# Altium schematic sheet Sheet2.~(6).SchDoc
size A4
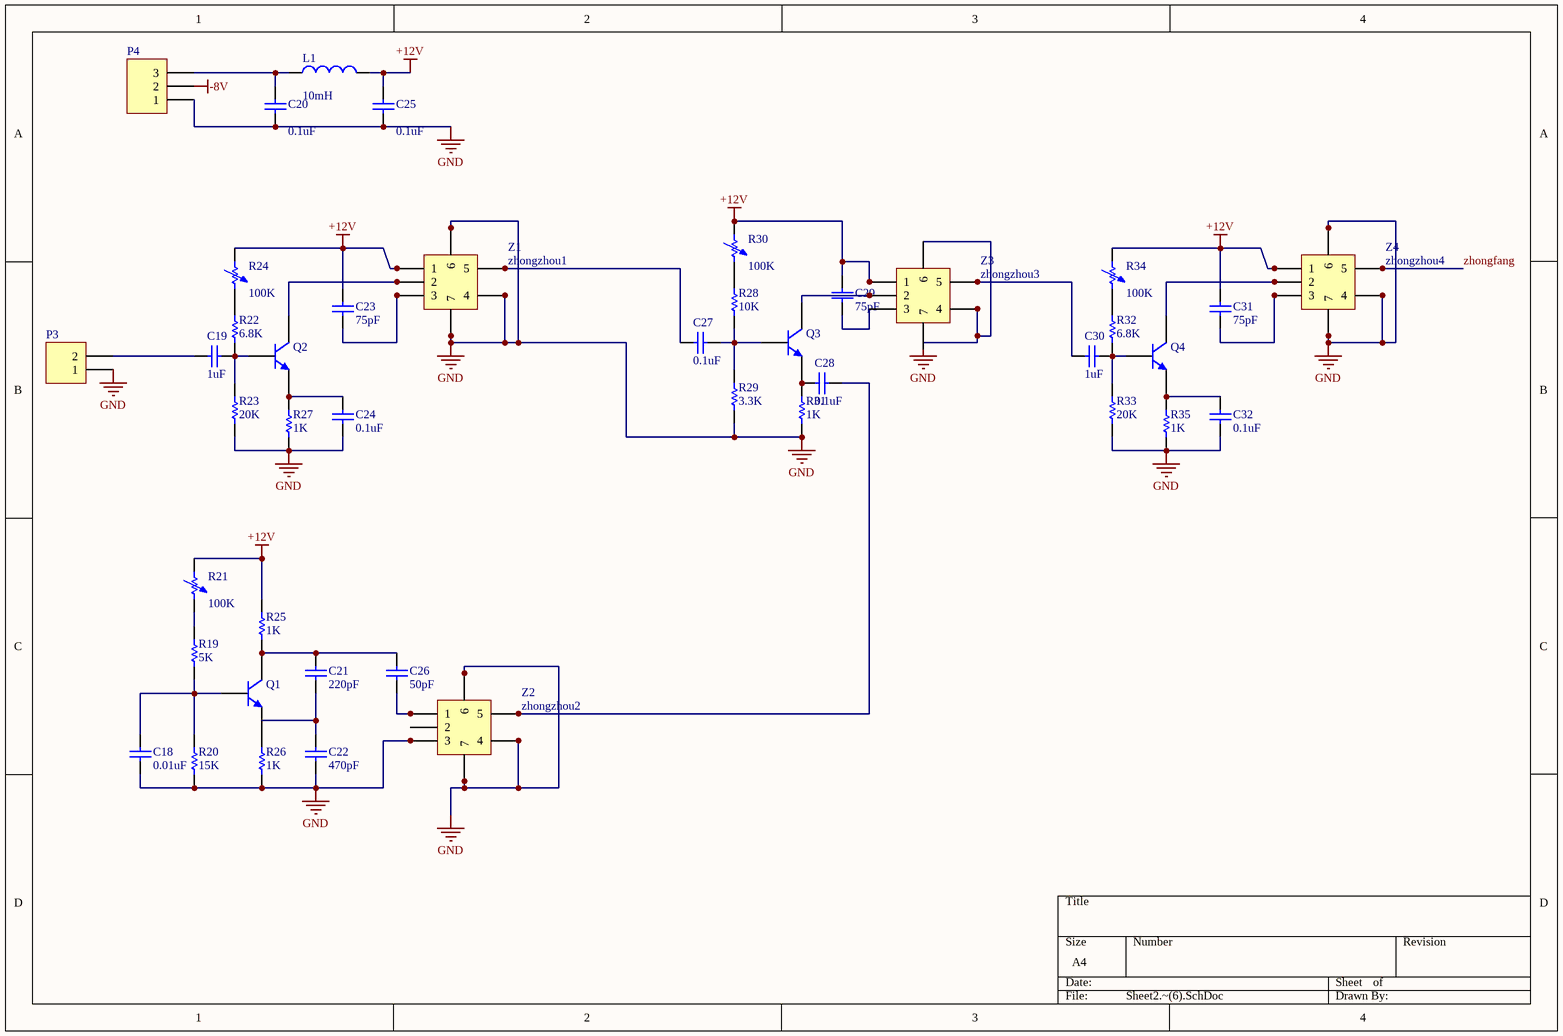
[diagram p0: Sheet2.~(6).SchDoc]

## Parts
C18  value 0.01uF  [2012[0805]]  (hidden comment: Cap)
C19  value 1uF  [2012[0805]]  (hidden comment: Cap)
C20  value 0.1uF  [2012[0805]]  (hidden comment: Cap)
C21  value 220pF  [2012[0805]]  (hidden comment: Cap)
C22  value 470pF  [2012[0805]]  (hidden comment: Cap)
C23  value 75pF  [2012[0805]]  (hidden comment: Cap)
C24  value 0.1uF  [2012[0805]]  (hidden comment: Cap)
C25  value 0.1uF  [2012[0805]]  (hidden comment: Cap)
C26  value 50pF  [2012[0805]]  (hidden comment: Cap)
C27  value 0.1uF  [2012[0805]]  (hidden comment: Cap)
C28  value 0.1uF  [2012[0805]]  (hidden comment: Cap)
C29  value 75pF  [2012[0805]]  (hidden comment: Cap)
C30  value 1uF  [2012[0805]]  (hidden comment: Cap)
C31  value 75pF  [2012[0805]]  (hidden comment: Cap)
C32  value 0.1uF  [2012[0805]]  (hidden comment: Cap)
L1  value 10mH  [0402-A]  (hidden comment: Inductor)
P3  Header 2  [HDR1X2]  (value not drawn)
P4  Header 3  [shuru]  (value not drawn)
Q1  NPN  [TO-226]  (value not drawn)
Q2  NPN  [TO-226]  (value not drawn)
Q3  NPN  [TO-226]  (value not drawn)
Q4  NPN  [TO-226]  (value not drawn)
R19  value 5K  [2012[0805]]  (hidden comment: Res1)
R20  value 15K  [2012[0805]]  (hidden comment: Res1)
R21  value 100K  [2012[0805]]  (hidden comment: Res Adj1)
R22  value 6.8K  [2012[0805]]  (hidden comment: Res1)
R23  value 20K  [2012[0805]]  (hidden comment: Res1)
R24  value 100K  [2012[0805]]  (hidden comment: Res Adj1)
R25  value 1K  [2012[0805]]  (hidden comment: Res1)
R26  value 1K  [2012[0805]]  (hidden comment: Res1)
R27  value 1K  [2012[0805]]  (hidden comment: Res1)
R28  value 10K  [2012[0805]]  (hidden comment: Res1)
R29  value 3.3K  [2012[0805]]  (hidden comment: Res1)
R30  value 100K  [2012[0805]]  (hidden comment: Res Adj1)
R31  value 1K  [2012[0805]]  (hidden comment: Res1)
R32  value 6.8K  [2012[0805]]  (hidden comment: Res1)
R33  value 20K  [2012[0805]]  (hidden comment: Res1)
R34  value 100K  [2012[0805]]  (hidden comment: Res Adj1)
R35  value 1K  [2012[0805]]  (hidden comment: Res1)
Z1  zhongzhou1  [zhongzhou]
Z2  zhongzhou2  [zhongzhou]
Z3  zhongzhou3  [zhongzhou]
Z4  zhongzhou4  [zhongzhou]

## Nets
+12V: C23.1 C25.2 C29.1 C31.1 L1.2 R21.1 R24.1 R25.2 R30.1 R34.1 Z1.1 Z3.1 Z4.1
-8V: P4.2
GND: C18.2 C20.1 C22.2 C24.1 C25.1 C32.1 P3.1 P4.1 R20.1 R23.1 R26.1 R27.1 R29.1 R31.1 R33.1 R35.1 Z1.4 Z1.6 Z1.7 Z2.3 Z2.4 Z2.6 Z2.7 Z3.4 Z3.6 Z4.4 Z4.6 Z4.7
zhongfang: Z4.5
NetC18_1: C18.1 Q1.2(B) R19.1 R20.2
NetC19_1: C19.1 P3.2
NetC19_2: C19.2 Q2.2(B) R22.1 R23.2
NetC20_2: C20.2 L1.1 P4.3
NetC21_1: C21.1 C26.2 Q1.1(C) R25.1
NetC21_2: C21.2 C22.1
NetC23_2: C23.2 Z1.3
NetC24_2: C24.2 Q2.3(E) R27.2
NetC26_1: C26.1 Z2.1
NetC27_1: C27.1 Z1.5
NetC27_2: C27.2 Q3.2(B) R28.1 R29.2
NetC28_1: C28.1 Q3.3(E) R31.2
NetC28_2: C28.2 Z2.5
NetC29_2: C29.2 Z3.3
NetC30_1: C30.1 Z3.5
NetC30_2: C30.2 Q4.2(B) R32.1 R33.2
NetC31_2: C31.2 Z4.3
NetC32_2: C32.2 Q4.3(E) R35.2
NetQ1_3: Q1.3(E) R26.2
NetQ2_1: Q2.1(C) Z1.2
NetQ3_1: Q3.1(C) Z3.2
NetQ4_1: Q4.1(C) Z4.2
NetR19_2: R19.2 R21.2
NetR22_2: R22.2 R24.2
NetR28_2: R28.2 R30.2
NetR32_2: R32.2 R34.2

Not connected (* = marked no-connect by the designer): Z2 2; Z3 7

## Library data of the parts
C18-C32 = Cap: Capacitor
L1 = Inductor: Code_IEC: 1005
P3 = Header 2: Header, 2-Pin
P4 = Header 3: Header, 3-Pin
Q1-Q4 = NPN: NPN Bipolar Transistor
R19 R20 R22 R23 R25-R29 R31-R33 R35 = Res1: Resistor
R21 R24 R30 R34 = Res Adj1: Variable Resistor; Set Position: 0.5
